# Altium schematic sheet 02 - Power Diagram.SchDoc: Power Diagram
size A3; PageSetup: Record=PageOptions¦CenterHorizontal=True¦CenterVertical=True¦PrintScale=0.70¦XCorrection=1.00¦YCorrection=1.00¦PrintKind=0¦BorderSize=5000000¦LeftOffset=0¦BottomOffset=0¦Orientation=2¦PaperLength=4200¦PaperWidth=2970¦Scale=100¦PaperSource=7¦PrintQuality=600¦MediaType=1¦DitherType=10¦PaperKind=A4¦PrintScaleMode=1; Author: Juan Anzola; SheetNumber: 2; SheetTotal: 21
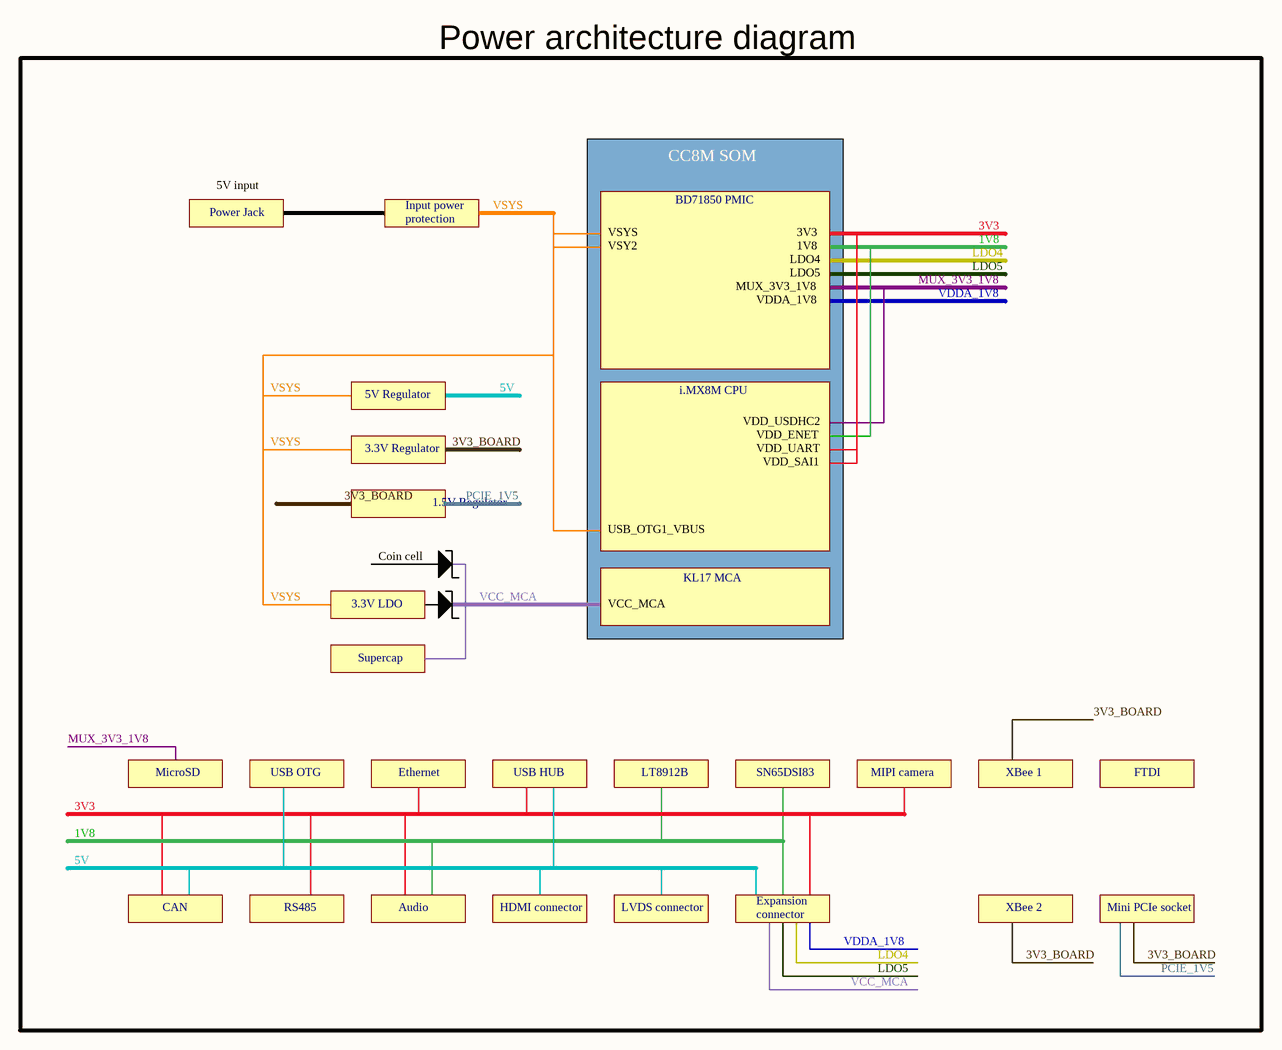
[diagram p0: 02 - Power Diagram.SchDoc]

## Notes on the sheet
- Power architecture diagram
- 5V input
- CC8M SOM
- BD71850 PMIC
- Power Jack
- Input power
- protection
- VSYS
- VSY2
- LDO4
- LDO5
- 3V3
- 1V8
- MUX_3V3_1V8
- VDDA_1V8
- 5V Regulator
- 5V
- i.MX8M CPU
- 3.3V Regulator
- 3V3_BOARD
- VDD_USDHC2
- VDD_ENET
- VDD_UART
- VDD_SAI1
- 1.5V Regulator
- PCIE_1V5
- USB_OTG1_VBUS
- 3.3V LDO
- Coin cell
- VCC_MCA
- KL17 MCA
- Supercap
- MicroSD
- USB OTG
- Ethernet
- USB HUB
- LT8912B
- SN65DSI83
- MIPI camera
- XBee 1
- FTDI
- CAN
- RS485
- Audio
- HDMI connector
- LVDS connector
- Expansion
- connector
- XBee 2
- Mini PCIe socket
